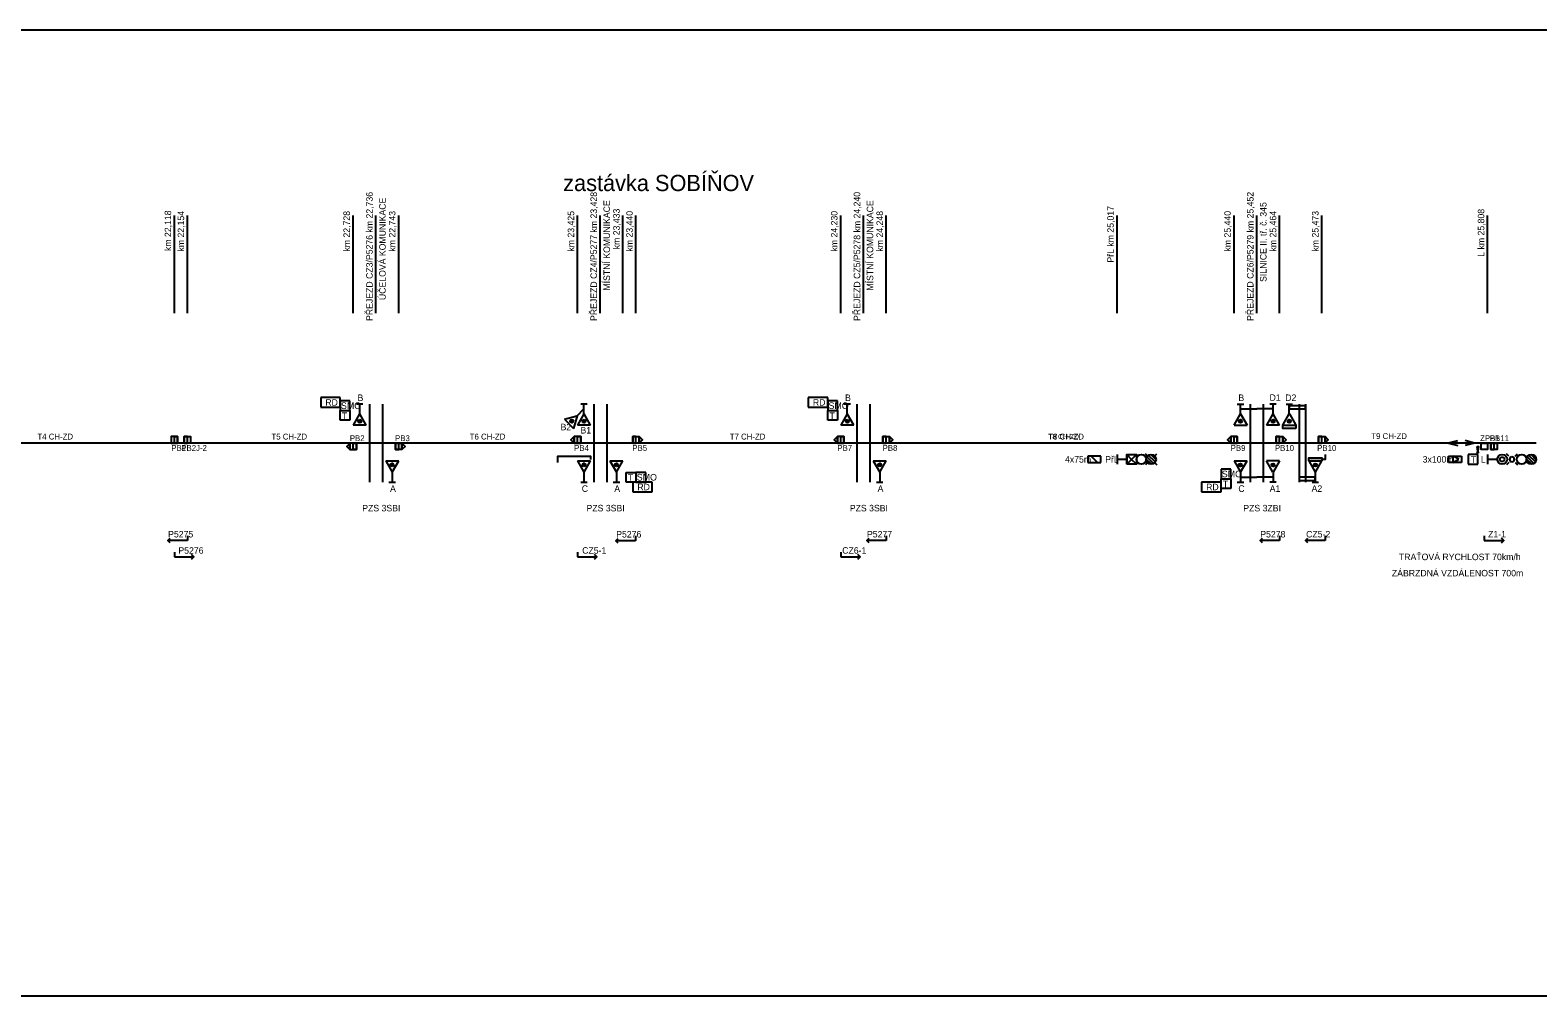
# Model space of a CAD drawing. Extents: x 2343 to 7744, y -5880 to 2050.
# Drawn here: x 5017.6 to 5481.5, y -5880 to -5583 of the extents above; entities that cross this region are included whole.
import ezdxf

# ---------------------------------------------------------------- set-up
doc = ezdxf.new("R2010")
doc.units = 0
for name, color, linetype in [('LISTY', 7, 'Continuous'), ('NAVRHOVANÉ', 7, 'Continuous'), ('Vrstva 1', 7, 'Continuous'), ('Vrstva 50', 7, 'Continuous'), ('VTO', 7, 'Continuous')]:
    doc.layers.add(name, color=color, linetype=linetype)

# ---------------------------------------------------------------- blocks, each defined once
blk = doc.blocks.new('SB113')
at = {"layer": 'Vrstva 1'}
for points in [[(10, 0), (-10, 0), (-10, -20), (10, -20)], [(0, 0), (10, 0), (10, -20), (0, -20)]]:
    blk.add_lwpolyline(points, close=True, dxfattribs=at)
blk = doc.blocks.new('P38')
at = {"layer": 'Vrstva 1'}
for p, q in [((0, 15), (0, 0)), ((0, 0), (60, 0))]:
    blk.add_line(p, q, dxfattribs=at)
blk.add_lwpolyline([(52.9, -7.1), (60, 0), (52.9, 7.1)], dxfattribs=at)
blk = doc.blocks.new('O9')
for p, q in [((1.512, 3.012), (-1.488, 3.012)), ((-1.488, 3.012), (-1.488, 0.012)), ((-1.488, 0.012), (1.512, 0.012)), ((1.512, 0.012), (1.512, 3.012))]:
    blk.add_line(p, q)
blk.add_text('T', height=2).set_placement((-0.664, 0.423))
blk = doc.blocks.new('O10')
at = {"layer": 'Vrstva 1'}
for p, q in [((3, 3), (-3, 3)), ((-3, 3), (-3, 0)), ((-3, 0), (3, 0)), ((3, 0), (3, 3))]:
    blk.add_line(p, q, dxfattribs=at)
blk.add_text('RD', height=2, dxfattribs=at).set_placement((-1.57, 0.503))
blk = doc.blocks.new('P21')
at = {"layer": 'Vrstva 1'}
for p, q in [((2.12, 2.15), (3.18, 6.01)), ((6.01, 3.18), (3.18, 6.01)), ((2.12, 2.12), (0, 0)), ((6.01, 3.18), (2.15, 2.12)), ((3.27, 3.56), (4.21, 3.56)), ((3.29, 3.93), (4.19, 3.93))]:
    blk.add_line(p, q, dxfattribs=at)
blk.add_circle((3.74, 3.72), 0.5, dxfattribs=at)
blk = doc.blocks.new('U3')
at = {"layer": 'Vrstva 1'}
for p, q in [((1, 4), (-1, 4)), ((-1, 4), (-1, 0)), ((-1, 1), (1, 3)), ((-1, 0), (1, 0)), ((1, 0), (1, 4))]:
    blk.add_line(p, q, dxfattribs=at)
blk = doc.blocks.new('NS30')
at = {"layer": 'Vrstva 1'}
for p, q in [((-1.499, 3.001), (0, 1.5)), ((1.499, 3.001), (-1.499, 3.001)), ((-1.499, 0), (0, 1.5)), ((1.499, 0), (-1.499, 0)), ((0, 1.5), (1.499, 3.001)), ((0, 1.5), (1.499, 0))]:
    blk.add_line(p, q, dxfattribs=at)
blk.add_lwpolyline([(-1.499, 3.001), (1.499, 3.001), (1.499, 0), (-1.499, 0)], close=True, dxfattribs=at)
blk = doc.blocks.new('U7')
at = {"layer": 'Vrstva 1'}
for p, q in [((-1, 4), (-1, 0)), ((1, 4), (-1, 4)), ((-1, 0), (1, 0)), ((-0.971, 1.411), (0.029, 3.143)), ((-0.971, 1.411), (1.029, 1.411)), ((0.029, 3.143), (1.029, 1.411)), ((1, 0), (1, 4))]:
    blk.add_line(p, q, dxfattribs=at)
blk = doc.blocks.new('O1')
for p, q in [((0.01, 0.066), (-2.895, 0.812)), ((0.01, 0.044), (-2.895, -0.702))]:
    blk.add_line(p, q)
blk = doc.blocks.new('NS44')
at = {"layer": 'Vrstva 1'}
blk.add_lwpolyline([(-3.8, 40), (3.7, 40), (0, 10)], close=True, dxfattribs=at)
blk.add_circle((0, 3.7), 3.75, dxfattribs=at)

msp = doc.modelspace()

# ---------------------------------------------------------------- linework, layer by layer
for p, q in [((5062, -5670), (5062, -5640)), ((5066, -5670), (5066, -5640)), ((5117, -5670), (5117, -5640)), ((5131, -5670), (5131, -5640)), ((5186, -5670), (5186, -5640)), ((5200, -5670), (5200, -5640)), ((5204, -5670), (5204, -5640)), ((5267, -5670), (5267, -5640)), ((5281, -5670), (5281, -5640)), ((5388, -5670), (5388, -5640)), ((5402, -5670), (5402, -5640)), ((5415, -5670), (5415, -5640)), ((5116, -5697), (5113, -5697)), ((5113, -5697), (5113, -5700)), ((5113, -5700), (5116, -5700)), ((5116, -5700), (5116, -5697)), ((5120, -5698), (5118, -5698)), ((5119, -5701.01), (5119, -5698)), ((5122, -5698), (5122, -5722)), ((5126, -5698), (5126, -5722)), ((5189, -5698), (5187, -5698)), ((5188, -5701.01), (5188, -5698)), ((5191, -5698), (5191, -5722)), ((5195, -5698), (5195, -5722)), ((5266, -5697), (5263, -5697)), ((5263, -5697), (5263, -5700)), ((5263, -5700), (5266, -5700)), ((5266, -5700), (5266, -5697)), ((5270, -5698), (5268, -5698)), ((5269, -5701.01), (5269, -5698)), ((5272, -5698), (5272, -5722)), ((5276, -5698), (5276, -5722)), ((5393, -5698), (5393, -5722)), ((5397, -5698), (5397, -5722)), ((5408, -5698), (5408, -5722)), ((5410, -5698), (5410, -5722)), ((5118.98, -5701.03), (5117, -5704.52)), ((5121, -5704.52), (5117, -5704.52)), ((5118.52, -5703.26), (5119.05, -5703.79)), ((5118.7, -5702.91), (5119.4, -5703.61)), ((5121, -5704.52), (5119.02, -5701.04)), ((5119.13, -5702.8), (5119.5, -5703.18)), ((5187.98, -5701.03), (5186, -5704.52)), ((5190, -5704.52), (5186, -5704.52)), ((5187.52, -5703.26), (5188.05, -5703.79)), ((5187.7, -5702.91), (5188.4, -5703.61)), ((5190, -5704.52), (5188.02, -5701.04)), ((5188.13, -5702.8), (5188.5, -5703.18)), ((5268.98, -5701.03), (5267, -5704.52)), ((5271, -5704.52), (5267, -5704.52)), ((5268.52, -5703.26), (5269.05, -5703.79)), ((5268.7, -5702.91), (5269.4, -5703.61)), ((5271, -5704.52), (5269.02, -5701.04)), ((5269.13, -5702.8), (5269.5, -5703.18)), ((5481, -5710), (4638, -5710)), ((5127, -5715.48), (5131, -5715.48)), ((5127, -5715.48), (5128.98, -5718.96)), ((5128.87, -5717.2), (5128.5, -5716.82)), ((5129.3, -5717.09), (5128.6, -5716.39)), ((5129.48, -5716.74), (5128.95, -5716.21)), ((5129, -5718.99), (5129, -5722)), ((5129.02, -5718.97), (5131, -5715.48)), ((5186, -5715.48), (5190, -5715.48)), ((5186, -5715.48), (5187.98, -5718.96)), ((5187.87, -5717.2), (5187.5, -5716.82)), ((5188.3, -5717.09), (5187.6, -5716.39)), ((5188.48, -5716.74), (5187.95, -5716.21)), ((5188, -5718.99), (5188, -5722)), ((5188.02, -5718.97), (5190, -5715.48)), ((5196, -5715.48), (5200, -5715.48)), ((5196, -5715.48), (5197.98, -5718.96)), ((5197.87, -5717.2), (5197.5, -5716.82)), ((5198.3, -5717.09), (5197.6, -5716.39)), ((5198.48, -5716.74), (5197.95, -5716.21)), ((5198, -5718.99), (5198, -5722)), ((5198.02, -5718.97), (5200, -5715.48)), ((5207, -5719), (5204, -5719)), ((5204, -5719), (5204, -5722)), ((5207, -5722), (5207, -5719)), ((5277, -5715.48), (5281, -5715.48)), ((5277, -5715.48), (5278.98, -5718.96)), ((5278.87, -5717.2), (5278.5, -5716.82)), ((5279.3, -5717.09), (5278.6, -5716.39)), ((5279.48, -5716.74), (5278.95, -5716.21)), ((5279, -5718.99), (5279, -5722)), ((5279.02, -5718.97), (5281, -5715.48)), ((5387, -5718), (5384, -5718)), ((5384, -5718), (5384, -5721)), ((5387, -5721), (5387, -5718)), ((5128, -5722), (5130, -5722)), ((5187, -5722), (5189, -5722)), ((5197, -5722), (5199, -5722)), ((5204, -5722), (5207, -5722)), ((5278, -5722), (5280, -5722)), ((5384, -5721), (5387, -5721)), ((5410, -5720.5), (5408, -5720.5))]:
    msp.add_line(p, q)
for points in [[(5405, -5699.5), (5410, -5699.5), (5410, -5698.5), (5405, -5698.5)], [(5407, -5705.5), (5403, -5705.5), (5403, -5704.5), (5407, -5704.5)], [(5415, -5715.5), (5411, -5715.5), (5411, -5714.5), (5415, -5714.5)], [(5408, -5721.5), (5413, -5721.5), (5413, -5720.5), (5408, -5720.5)]]:
    msp.add_lwpolyline(points, close=True)
msp.add_lwpolyline([(5180, -5716), (5180, -5714), (5190, -5714), (5190, -5715)])
for centre, major_axis in [((5119.02, -5703.29), (0, 0.502)), ((5188.02, -5703.29), (0, 0.502)), ((5269.02, -5703.29), (0, 0.502)), ((5128.98, -5716.71), (0, -0.502)), ((5187.98, -5716.71), (0, -0.502)), ((5197.98, -5716.71), (0, -0.502)), ((5278.98, -5716.71), (0, -0.502))]:
    msp.add_ellipse(centre, major_axis=major_axis, ratio=0.996169)
at = {"layer": 'NAVRHOVANÉ'}
for p, q in [((5352, -5670), (5352, -5640)), ((5466, -5670), (5466, -5640)), ((5352, -5713.5), (5352, -5716.5)), ((5361.5, -5714), (5360.8, -5713.3)), ((5363.25, -5716.3), (5361.2, -5714.2)), ((5363.7, -5715.8), (5361.7, -5713.8)), ((5364, -5715.1), (5362.4, -5713.5)), ((5363.5, -5714), (5364.2, -5713.3)), ((5466, -5713.5), (5466, -5716.5)), ((5472.5, -5714), (5471.8, -5713.3)), ((5474.5, -5714), (5475.2, -5713.3)), ((5480.25, -5716.3), (5478.2, -5714.2)), ((5480.7, -5715.8), (5478.7, -5713.8)), ((5481, -5715.1), (5479.4, -5713.5)), ((5355, -5715), (5352, -5715)), ((5361.5, -5716), (5360.8, -5716.7)), ((5362.6, -5716.5), (5361, -5714.9)), ((5363.5, -5716), (5364.2, -5716.7)), ((5469, -5715), (5466, -5715)), ((5472.5, -5716), (5471.8, -5716.7)), ((5474.5, -5716), (5475.2, -5716.7)), ((5479.6, -5716.5), (5478, -5714.9))]:
    msp.add_line(p, q, dxfattribs=at)
for points in [[(5185, -5708), (5184, -5709), (5185, -5710)], [(5205, -5708), (5206, -5709), (5205, -5710)], [(5266, -5708), (5265, -5709), (5266, -5710)], [(5282, -5708), (5283, -5709), (5282, -5710)], [(5387, -5708), (5386, -5709), (5387, -5710)], [(5403, -5708), (5404, -5709), (5403, -5710)], [(5416, -5708), (5417, -5709), (5416, -5710)], [(5116, -5710), (5115, -5711), (5116, -5712)], [(5132, -5710), (5133, -5711), (5132, -5712)], [(5464, -5710), (5466, -5710), (5466, -5712), (5464, -5712)]]:
    msp.add_lwpolyline(points, close=True, dxfattribs=at)
for centre, radius in [((5359.5, -5715), 1.5), ((5362.5, -5715), 1.5), ((5470.5, -5715), 1.5), ((5470.5, -5715), 0.7), ((5476.5, -5715), 1.5), ((5479.5, -5715), 1.5)]:
    msp.add_circle(centre, radius, dxfattribs=at)
for start, end in [(90, 270), (270, 90)]:
    msp.add_arc((5473.5, -5715), 0.75, start, end, dxfattribs=at)
at = {"layer": 'Vrstva 1'}
for p, q in [((5389, -5698), (5391, -5698)), ((5390, -5701), (5390, -5698)), ((5390, -5699.5), (5395, -5699.5)), ((5400, -5699.5), (5395, -5699.5)), ((5401, -5698), (5399, -5698)), ((5400, -5701), (5400, -5698)), ((5404, -5698), (5406, -5698)), ((5405, -5701), (5405, -5698)), ((5405, -5699.5), (5410, -5699.5)), ((5388, -5704.5), (5389.98, -5701.03)), ((5388, -5704.5), (5392, -5704.5)), ((5389.87, -5702.79), (5389.5, -5703.16)), ((5390.3, -5702.89), (5389.6, -5703.59)), ((5390.48, -5703.24), (5389.95, -5703.77)), ((5390.02, -5701.02), (5392, -5704.5)), ((5399.98, -5701.02), (5398, -5704.5)), ((5402, -5704.5), (5398, -5704.5)), ((5399.52, -5703.24), (5400.05, -5703.77)), ((5399.7, -5702.89), (5400.4, -5703.59)), ((5402, -5704.5), (5400.02, -5701.03)), ((5400.13, -5702.79), (5400.5, -5703.16)), ((5403, -5704.5), (5404.98, -5701.03)), ((5403, -5704.5), (5407, -5704.5)), ((5404.87, -5702.79), (5404.5, -5703.16)), ((5405.3, -5702.89), (5404.6, -5703.59)), ((5405.48, -5703.24), (5404.95, -5703.77)), ((5405.02, -5701.02), (5407, -5704.5)), ((5388, -5715.5), (5392, -5715.5)), ((5388, -5715.5), (5389.98, -5718.98)), ((5389.87, -5717.21), (5389.5, -5716.84)), ((5390.3, -5717.11), (5389.6, -5716.41)), ((5390.48, -5716.76), (5389.95, -5716.23)), ((5390, -5719), (5390, -5722)), ((5390.02, -5718.98), (5392, -5715.5)), ((5399.98, -5718.98), (5398, -5715.5)), ((5402, -5715.5), (5398, -5715.5)), ((5399.52, -5716.76), (5400.05, -5716.23)), ((5399.7, -5717.11), (5400.4, -5716.41)), ((5400, -5719), (5400, -5722)), ((5402, -5715.5), (5400.02, -5718.98)), ((5400.13, -5717.21), (5400.5, -5716.84)), ((5411, -5715.5), (5415, -5715.5)), ((5411, -5715.5), (5412.98, -5718.98)), ((5412.91, -5717.22), (5412.49, -5716.8)), ((5413.32, -5717.1), (5412.61, -5716.39)), ((5413.48, -5716.73), (5412.98, -5716.23)), ((5413, -5719), (5413, -5722)), ((5413.02, -5718.98), (5415, -5715.5)), ((5389, -5722), (5391, -5722)), ((5390, -5720.5), (5395, -5720.5)), ((5400, -5720.5), (5395, -5720.5)), ((5401, -5722), (5399, -5722)), ((5412, -5722), (5414, -5722))]:
    msp.add_line(p, q, dxfattribs=at)
for points in [[(5411, -5715.5), (5411, -5714.5), (5415, -5714.5), (5415, -5715.5)], [(5416, -5713.5), (5416, -5715), (5415, -5715)]]:
    msp.add_lwpolyline(points, dxfattribs=at)
for centre in [(5389.98, -5703.27), (5400.02, -5703.27), (5404.98, -5703.27), (5389.98, -5716.73), (5400.02, -5716.73), (5412.98, -5716.73)]:
    msp.add_circle(centre, 0.5, dxfattribs=at)
at = {"layer": 'Vrstva 50'}
for p, q in [((5124, -5670), (5124, -5640)), ((5193, -5670), (5193, -5640)), ((5274, -5670), (5274, -5640)), ((5395, -5670), (5395, -5640))]:
    msp.add_line(p, q, dxfattribs=at)
msp.add_lwpolyline([(4570, -5880), (5830, -5880), (5830, -5583), (4570, -5583)], close=True, dxfattribs=at)

# ---------------------------------------------------------------- block references
for p in [(5110, -5699), (5260, -5699), (5206, -5725), (5381, -5725)]:
    msp.add_blockref('O10', p)
at = {"rotation": 180}
msp.add_blockref('P21', (5188, -5699.51), dxfattribs=at)
at = {"xscale": 0.1, "yscale": 0.10000000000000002}
for p in [(5062, -5708), (5186, -5708), (5267, -5708), (5388, -5708), (5117, -5710)]:
    msp.add_blockref('SB113', p, dxfattribs=at)
at = {"xscale": 0.1, "yscale": -0.10000000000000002, "rotation": 180}
for p in [(5066, -5708), (5204, -5708), (5281, -5708), (5402, -5708), (5415, -5708), (5131, -5710), (5468, -5710)]:
    msp.add_blockref('SB113', p, dxfattribs=at)
at = {"layer": 'LISTY', "xscale": 0.05, "yscale": 0.05000000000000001}
msp.add_blockref('NS44', (5463, -5713), dxfattribs=at)
at = {"layer": 'NAVRHOVANÉ'}
for name, p, rotation in [('O1', (5454.01, -5709.91), 180), ('U3', (5343, -5715), -90.00000000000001), ('NS30', (5358, -5715), 90)]:
    msp.add_blockref(name, p, dxfattribs=dict(at, rotation=rotation))
msp.add_blockref('O1', (5461.99, -5710.04), dxfattribs=at)
at = {"layer": 'NAVRHOVANÉ', "yscale": -1, "rotation": 90.00000000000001}
msp.add_blockref('U7', (5454, -5715), dxfattribs=at)
at = {"layer": 'NAVRHOVANÉ', "xscale": 0.1, "yscale": -0.10000000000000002, "rotation": 180}
for p in [(5066, -5740), (5203.85, -5740.02), (5281, -5740), (5402, -5740), (5416, -5740)]:
    msp.add_blockref('P38', p, dxfattribs=at)
at = {"layer": 'NAVRHOVANÉ', "xscale": 0.1, "yscale": 0.10000000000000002}
for p in [(5465, -5740), (5062, -5745), (5186, -5745), (5267, -5745)]:
    msp.add_blockref('P38', p, dxfattribs=at)
at = {"layer": 'VTO', "yscale": -1, "rotation": 180}
for p in [(5114.51, -5703.01), (5264.51, -5703.01), (5202.51, -5722.01), (5385.51, -5724.01)]:
    msp.add_blockref('O9', p, dxfattribs=at)
at = {"layer": 'VTO'}
msp.add_blockref('O9', (5461.49, -5716.51), dxfattribs=at)

# ---------------------------------------------------------------- texts
for s, height, p in [('zastávka SOBÍŇOV', 5, (5181.61, -5632.5)), ('B', 2, (5118.35, -5697.05)), ('B', 2, (5268.35, -5697.05)), ('B', 2, (5389.35, -5697.05)), ('B', 2, (5389.35, -5697.05)), ('D1', 2, (5398.93, -5697)), ('D2', 2, (5403.76, -5697.05)), ('SMO', 2.044, (5113.23, -5699.52)), ('SMO', 2.044, (5263.23, -5699.52)), ('B2', 2, (5180.81, -5706.05)), ('B1', 2, (5186.94, -5707.05)), ('SMO', 2.044, (5384.23, -5720.52)), ('A', 2, (5128.35, -5725)), ('C', 2, (5187.33, -5725)), ('A', 2, (5197.35, -5725)), ('SMO', 2.044, (5204.23, -5721.52)), ('A', 2, (5278.35, -5725)), ('C', 2, (5389.33, -5725)), ('A1', 2, (5398.98, -5725)), ('A2', 2, (5411.86, -5725)), ('PZS 3SBI', 2, (5119.79, -5731)), ('PZS 3SBI', 2, (5188.79, -5731)), ('PZS 3SBI', 2, (5269.79, -5731)), ('PZS 3ZBI', 2, (5390.85, -5731)), ('TRAŤOVÁ RYCHLOST 70km/h', 2, (5438.74, -5746)), ('ZÁBRZDNÁ VZDÁLENOST 700m', 2, (5436.56, -5751))]:
    msp.add_text(s, height=height).set_placement(p)
for s, p in [('km 22,118', (5061, -5650.94)), ('km 22,154', (5065, -5651.08)), ('km 22,728', (5116, -5651.09)), ('km 22,743', (5130, -5651.09)), ('km 23,425', (5185, -5651.1)), ('km 23,433', (5199, -5650.39)), ('km 23,440', (5203, -5651.08)), ('km 24,230', (5266, -5651.08)), ('km 24,248', (5280, -5651.09)), ('km 25,440', (5387, -5651.08)), ('SILNICE II. tř. č. 345', (5398, -5660.43)), ('km 25,464', (5401, -5651.08)), ('km 25,473', (5414, -5651.09))]:
    msp.add_text(s, height=2, rotation=90).set_placement(p)
at = {"layer": 'NAVRHOVANÉ'}
for s, p in [('PřL km 25,017', (5351, -5654.48)), ('L km 25,808', (5465, -5652.69))]:
    msp.add_text(s, height=2, rotation=90, dxfattribs=at).set_placement(p)
for s, height, p in [('T4 CH-ZD', 1.8, (5019.86, -5708.9)), ('T5 CH-ZD', 1.8, (5091.86, -5708.9)), ('PB2', 1.8, (5115.97, -5709.4)), ('PB3', 1.8, (5129.88, -5709.4)), ('T6 CH-ZD', 1.8, (5152.86, -5708.9)), ('T7 CH-ZD', 1.8, (5232.86, -5708.9)), ('T8 CH-ZD', 1.5, (5330.86, -5708.75)), ('T8 CH-ZD', 1.8, (5330.86, -5708.9)), ('T9 CH-ZD', 1.8, (5430.23, -5708.75)), ('ZPB1', 1.8, (5463.7, -5709.4)), ('PB11', 1.8, (5466.69, -5709.4)), ('PB1', 1.8, (5061.05, -5712.4)), ('PB2J-2', 1.8, (5064.11, -5712.4)), ('PB4', 1.8, (5184.97, -5712.4)), ('PB5', 1.8, (5202.88, -5712.4)), ('PB7', 1.8, (5265.97, -5712.4)), ('PB8', 1.8, (5279.88, -5712.4)), ('4x75m', 2, (5336, -5716)), ('PřL', 2, (5348.37, -5716)), ('PB9', 1.8, (5386.97, -5712.4)), ('PB10', 1.8, (5400.57, -5712.4)), ('PB10', 1.8, (5413.57, -5712.4)), ('3x100m', 2, (5446.04, -5716)), ('L', 2, (5463.94, -5716)), ('P5275', 2, (5060.06, -5739.02)), ('P5276', 2, (5197.92, -5739.04)), ('P5277', 2, (5275.07, -5739.02)), ('P5278', 2, (5396.07, -5739.02)), ('CZ5-2', 2, (5410.18, -5739.02)), ('Z1-1', 2, (5466.17, -5739.02)), ('P5276', 2, (5063.22, -5744.02)), ('CZ5-1', 2, (5187.46, -5744.02)), ('CZ6-1', 2, (5267.46, -5744.02))]:
    msp.add_text(s, height=height, dxfattribs=at).set_placement(p)
at = {"layer": 'Vrstva 50'}
for s, p in [('PŘEJEZD CZ3/P5276 km 22,736', (5123, -5672.44)), ('ÚČELOVÁ KOMUNIKACE', (5127, -5666.02)), ('PŘEJEZD CZ4/P5277 km 23,428', (5192, -5672.44)), ('MÍSTNÍ KOMUNIKACE', (5196, -5663.1)), ('PŘEJEZD CZ5/P5278 km 24,240', (5273, -5672.43)), ('MÍSTNÍ KOMUNIKACE', (5277, -5663.1)), ('PŘEJEZD CZ6/P5279 km 25,452', (5394, -5672.42))]:
    msp.add_text(s, height=2, rotation=90, dxfattribs=at).set_placement(p)

doc.saveas('drawing.dxf')
